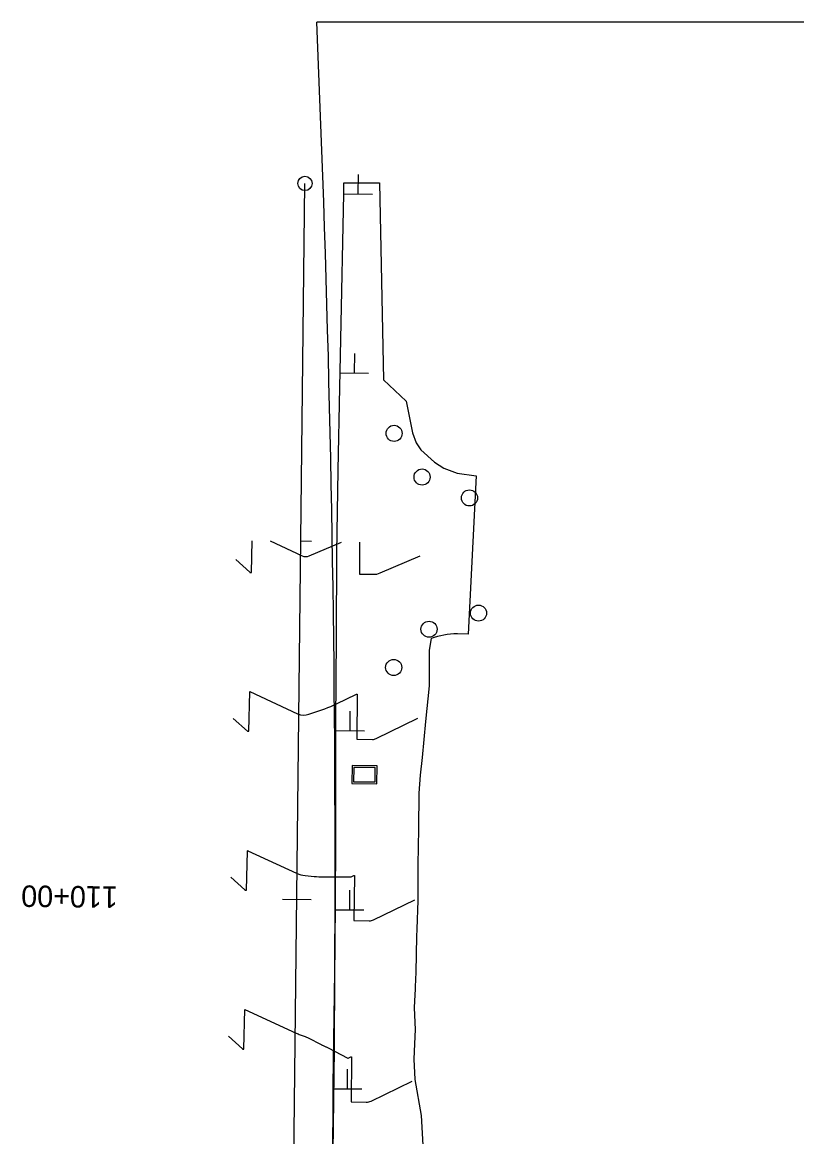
# Model space of a CAD drawing. Extents: x 1710723 to 1713003, y 548603 to 551142.
# Drawn here: x 1712408.5 to 1712624.8, y 550831.1 to 551142.3 of the extents above; entities that cross this region are included whole.
import ezdxf

# ---------------------------------------------------------------- set-up
doc = ezdxf.new("R2010")
doc.units = 0
for name, color, linetype in [('R_Contours', 7, 'Continuous'), ('R_Horz Alg', 7, 'Continuous'), ('R_Horz Alg Annot', 7, 'Continuous'), ('R_MOT', 7, 'Continuous'), ('R_No Plot', 7, 'Continuous'), ('R_Striping', 7, 'Continuous'), ('R_Water', 7, 'Continuous')]:
    doc.layers.add(name, color=color, linetype=linetype)

msp = doc.modelspace()

# ---------------------------------------------------------------- linework, layer by layer
at = {"layer": 'R_Contours'}
for points in [[(1712468.14, 550992.29), (1712472.02, 550988.74), (1712472.05, 550988.71), (1712472.09, 550988.69), (1712472.14, 550988.68), (1712472.18, 550988.67), (1712472.49, 550988.67), (1712472.5, 550988.67), (1712472.5, 550988.67), (1712472.5, 550988.67), (1712472.5, 550988.68), (1712472.71, 550997.54)], [(1712477.72, 550997.46), (1712486.7, 550993.31), (1712487.18, 550993.14), (1712487.66, 550993.08), (1712488.14, 550993.13), (1712488.62, 550993.28), (1712497.72, 550997.15)], [(1712502.74, 550997.08), (1712502.67, 550988.29), (1712502.67, 550988.25), (1712502.69, 550988.22), (1712502.72, 550988.2), (1712502.76, 550988.2), (1712506.58, 550988.14), (1712507.08, 550988.16), (1712507.56, 550988.22), (1712508.04, 550988.34), (1712508.5, 550988.51), (1712519.66, 550993.26)], [(1712467.45, 550947.91), (1712471.37, 550944.32), (1712471.38, 550944.31), (1712471.4, 550944.31), (1712471.41, 550944.3), (1712471.43, 550944.3), (1712471.74, 550944.3), (1712471.77, 550944.3), (1712471.8, 550944.31), (1712471.81, 550944.33), (1712471.82, 550944.36), (1712472.07, 550955.35), (1712472.07, 550955.37), (1712472.08, 550955.38), (1712472.09, 550955.38), (1712472.1, 550955.37), (1712485.4, 550949.22), (1712486.19, 550948.94), (1712486.98, 550948.82), (1712487.78, 550948.86), (1712488.59, 550949.06), (1712493.02, 550950.6), (1712493.85, 550950.91), (1712494.67, 550951.23), (1712495.48, 550951.58), (1712496.28, 550951.96), (1712501.86, 550954.68), (1712501.95, 550954.71), (1712502.01, 550954.69), (1712502.05, 550954.64), (1712502.06, 550954.55), (1712501.95, 550942.16), (1712501.95, 550942.14), (1712501.96, 550942.12), (1712501.98, 550942.11), (1712502, 550942.11), (1712506.31, 550942.04), (1712506.58, 550942.05), (1712506.85, 550942.1), (1712507.11, 550942.17), (1712507.37, 550942.28), (1712518.96, 550947.93)], [(1712466.76, 550903.54), (1712470.65, 550899.98), (1712470.68, 550899.96), (1712470.71, 550899.94), (1712470.75, 550899.93), (1712470.79, 550899.93), (1712471.1, 550899.92), (1712471.11, 550899.92), (1712471.12, 550899.93), (1712471.12, 550899.93), (1712471.12, 550899.95), (1712471.37, 550910.83), (1712471.39, 550910.9), (1712471.42, 550910.95), (1712471.47, 550910.96), (1712471.55, 550910.93), (1712485.13, 550904.65), (1712485.71, 550904.41), (1712486.3, 550904.23), (1712486.91, 550904.09), (1712487.53, 550904.01), (1712490.04, 550903.77), (1712490.67, 550903.72), (1712491.3, 550903.68), (1712491.92, 550903.66), (1712492.55, 550903.65), (1712500.17, 550903.62), (1712500.22, 550903.62), (1712500.26, 550903.63), (1712500.31, 550903.64), (1712500.35, 550903.66), (1712501.11, 550904.03), (1712501.18, 550904.05), (1712501.23, 550904.04), (1712501.26, 550904), (1712501.27, 550903.92), (1712501.16, 550891.5), (1712501.16, 550891.47), (1712501.18, 550891.45), (1712501.19, 550891.44), (1712501.22, 550891.44), (1712505.44, 550891.37), (1712505.76, 550891.39), (1712506.06, 550891.43), (1712506.36, 550891.52), (1712506.65, 550891.64), (1712518.17, 550897.26)], [(1712466.07, 550859.17), (1712470.01, 550855.56), (1712470.01, 550855.56), (1712470.02, 550855.56), (1712470.02, 550855.55), (1712470.03, 550855.55), (1712470.34, 550855.55), (1712470.38, 550855.55), (1712470.41, 550855.57), (1712470.43, 550855.6), (1712470.43, 550855.64), (1712470.69, 550866.61), (1712470.69, 550866.62), (1712470.69, 550866.63), (1712470.7, 550866.63), (1712470.71, 550866.63), (1712485.03, 550860), (1712485.31, 550859.88), (1712485.59, 550859.76), (1712485.87, 550859.65), (1712486.15, 550859.54), (1712487.29, 550859.13), (1712487.57, 550859.02), (1712487.85, 550858.91), (1712488.13, 550858.78), (1712488.4, 550858.65), (1712491.97, 550856.81), (1712492.11, 550856.74), (1712492.25, 550856.67), (1712492.39, 550856.6), (1712492.54, 550856.53), (1712493.26, 550856.2), (1712493.43, 550856.12), (1712493.6, 550856.04), (1712493.77, 550855.95), (1712493.93, 550855.87), (1712499.4, 550852.99), (1712499.44, 550852.97), (1712499.48, 550852.97), (1712499.52, 550852.97), (1712499.56, 550852.99), (1712500.32, 550853.35), (1712500.39, 550853.38), (1712500.44, 550853.37), (1712500.47, 550853.33), (1712500.48, 550853.25), (1712500.37, 550840.83), (1712500.38, 550840.81), (1712500.39, 550840.79), (1712500.41, 550840.77), (1712500.44, 550840.77), (1712504.58, 550840.7), (1712504.93, 550840.72), (1712505.27, 550840.77), (1712505.6, 550840.87), (1712505.93, 550841), (1712517.38, 550846.59)]]:
    msp.add_lwpolyline(points, dxfattribs=at)
at = {"layer": 'R_Horz Alg'}
msp.add_line((1712484.19, 550809.05), (1712487.46, 551097.32), dxfattribs=at)
at = {"layer": 'R_Horz Alg Annot'}
for points in [[(1712489.33, 550997.35), (1712486.33, 550997.39)], [(1712481.19, 550897.44), (1712489.19, 550897.35)]]:
    msp.add_lwpolyline(points, dxfattribs=at)
msp.add_circle((1712487.46, 551097.32), 2, dxfattribs=at)
at = {"layer": 'R_MOT'}
for p, q in [((1712498.33, 551097.48), (1712508.33, 551097.46)), ((1712502.32, 551094.39), (1712502.43, 551099.85)), ((1712508.33, 551097.46), (1712509.43, 551042.44)), ((1712506.29, 551094.19), (1712498.29, 551094.36)), ((1712501.27, 551044.4), (1712501.38, 551049.86)), ((1712505.25, 551044.2), (1712497.25, 551044.37)), ((1712500.11, 550944.49), (1712500.12, 550949.95)), ((1712504.09, 550944.37), (1712496.09, 550944.38)), ((1712499.96, 550894.48), (1712499.99, 550899.94)), ((1712503.94, 550894.34), (1712495.94, 550894.38)), ((1712499.33, 550844.48), (1712499.35, 550849.94)), ((1712503.31, 550844.35), (1712495.31, 550844.38))]:
    msp.add_line(p, q, dxfattribs=at)
for points in [[(1712493.77, 550713.62), (1712493.83, 550720.08), (1712494.05, 550740.6), (1712494.26, 550761.12), (1712494.59, 550779.89), (1712494.68, 550785.07), (1712495.11, 550798.25), (1712495.22, 550821.87), (1712495.32, 550845.5), (1712495.61, 550864.5), (1712495.9, 550883.5), (1712495.97, 550897.95), (1712496.05, 550912.4), (1712496.08, 550929.64), (1712496.11, 550946.87), (1712496.25, 550970.48), (1712496.4, 550994.08), (1712496.78, 551017.19), (1712497.17, 551040.29), (1712497.46, 551053.82), (1712497.74, 551067.34), (1712498.02, 551080.87), (1712498.31, 551094.4), (1712498.33, 551097.48)], [(1712509.43, 551042.44), (1712515.73, 551036.46), (1712517.54, 551027.64), (1712518.51, 551024.91), (1712519.83, 551022.93), (1712523.61, 551019.48), (1712526.3, 551017.83), (1712530.01, 551016.36), (1712535.29, 551015.62), (1712533.04, 550971.47), (1712530.04, 550971.5)], [(1712522.69, 550970.19), (1712522.15, 550966.98), (1712522.17, 550958.63), (1712522.19, 550956.98), (1712521.18, 550946.99), (1712520.2, 550937), (1712519.69, 550932.01), (1712519.27, 550927.01), (1712519.14, 550917.01), (1712519, 550907.01), (1712518.97, 550898.39), (1712518.97, 550897.01), (1712518.97, 550897.01), (1712518.73, 550889.02), (1712518.65, 550887.01), (1712518.41, 550877.02), (1712518.24, 550872.96), (1712518.21, 550872.27), (1712518.07, 550869.02), (1712517.99, 550867.02), (1712518.22, 550861.02), (1712518.04, 550857.02), (1712517.85, 550852.72), (1712518.19, 550847.02), (1712519.92, 550837), (1712520.48, 550826.99)]]:
    msp.add_lwpolyline(points, dxfattribs=at)
for centre in [(1712512.37, 551027.51), (1712520.18, 551015.31), (1712533.42, 551009.48), (1712535.95, 550977.31), (1712522.13, 550972.8), (1712512.26, 550962.13)]:
    msp.add_circle(centre, 2.25, dxfattribs=at)
msp.add_arc((1712529.81, 550951.5), 20, 89.3498, 110.8496, dxfattribs=at)
at = {"layer": 'R_No Plot'}
msp.add_line((1713002.92, 551142.32), (1712490.77, 551142.33), dxfattribs=at)
msp.add_arc((1706966.7, 550904.53), 5529.19, 357.70822, 2.46492, dxfattribs=at)
at = {"layer": 'R_Striping'}
msp.add_line((1712484.19, 550809.05), (1712487.46, 551097.32), dxfattribs=at)
at = {"layer": 'R_Water'}
for points in [[(1712507.56, 550929.65), (1712507.62, 550934.64), (1712500.62, 550934.72), (1712500.56, 550929.72)], [(1712507.06, 550930.15), (1712507.11, 550934.15), (1712501.11, 550934.22), (1712501.06, 550930.22)]]:
    msp.add_lwpolyline(points, close=True, dxfattribs=at)

# ---------------------------------------------------------------- texts
at = {"layer": 'R_Horz Alg Annot'}
msp.add_text('110+00', height=6, rotation=179.3498, dxfattribs=at).set_placement((1712435.23, 550900.96))

doc.saveas('drawing.dxf')
